// Mitsubishi GX Works2 project: 22.2种产品分别延时自断（MOV指令）   PLC: FX3U/FX3UC

PROGRAM MAIN
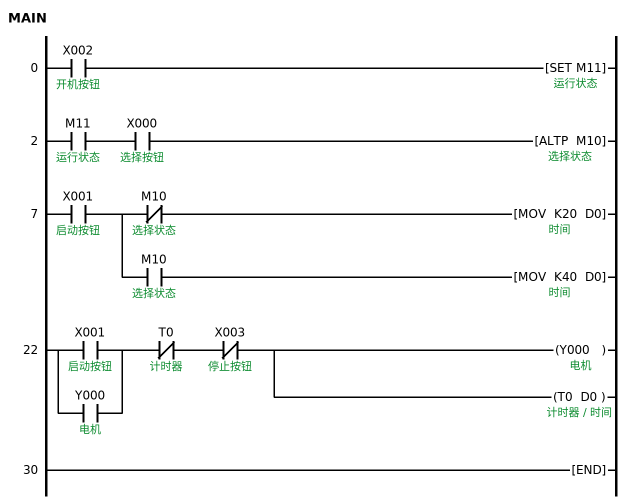
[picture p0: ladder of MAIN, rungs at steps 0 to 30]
0     LD      X002  ; 开机按钮
      SET     M11  ; 运行状态
2     LD      M11  ; 运行状态
      AND     X000  ; 选择按钮
      ALTP    M10  ; 选择状态
7     LD      X001  ; 启动按钮
      MPS
      ANI     M10  ; 选择状态
      MOV     K20 D0  ; 时间
        [note] 选择ON时，计时2秒到D0
      MPP
      AND     M10  ; 选择状态
      MOV     K40 D0
        [note] 选择OFF时，计时4秒到D0
22    LD      X001  ; 启动按钮
      OR      Y000  ; 电机
      ANI     T0  ; 计时器
      ANI     X003  ; 停止按钮
      OUT     Y000  ; 电机
      OUT     T0 D0  ; 计时器 / 时间
        [note] 由D0的值决定时间
30    END
END_PROGRAM

// device comments not shown above
M1  ; OFF，小产品
M2  ; 选择状态
M20  ; 计时器中转
M21  ; 2秒计时器中转
T1  ; 延时2秒停止
T20  ; 延时2秒
T40  ; 延时4秒
D1  ; 选择OFF状态
